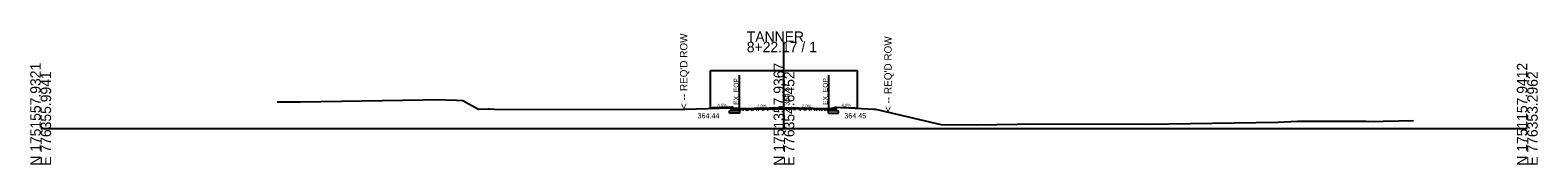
# Model space of a CAD drawing. Extents: x 774192 to 776597, y 1750236 to 1752784.
# Drawn here: x 774680.5 to 775086.2, y 1750248.9 to 1750284.7 of the extents above; entities that cross this region are included whole.
import ezdxf

# ---------------------------------------------------------------- set-up
doc = ezdxf.new("R2010")
doc.units = 0
for name, color, linetype in [('ControlPoints', 7, 'Continuous'), ('Default', 7, 'Continuous'), ('Observations', 7, 'Continuous'), ('Setups', 7, 'Continuous'), ('SHEET_BORDER_TX', 7, 'Continuous'), ('SHEET_DATE_DGN_TX', 7, 'Continuous'), ('SHEET_LOGO', 7, 'Continuous'), ('SHEET_PLOTTING_SHAPE', 7, 'Continuous'), ('SHEET_PRELIM', 7, 'Continuous'), ('SHEET_PROJ_NUMBER', 7, 'Continuous'), ('SHEET_TITLE_BLOCK_TX', 7, 'Continuous'), ('TS_BACKBONE', 7, 'Continuous'), ('TS_DIMENSIONS', 7, 'Continuous')]:
    doc.layers.add(name, color=color, linetype=linetype)

msp = doc.modelspace()

# ---------------------------------------------------------------- linework, layer by layer
at = {"layer": 'ControlPoints'}
msp.add_lwpolyline([(774746.94, 1750265.76), (774748.9, 1750265.76), (774753.28, 1750265.74), (774786.2, 1750266.31), (774789.35, 1750266.35), (774795.18, 1750266.18), (774796.95, 1750266.12), (774801.15, 1750263.79), (774803.7, 1750263.89), (774804.05, 1750263.87), (774805.45, 1750263.8), (774853.5, 1750263.73), (774869.1, 1750264.16), (774870.94, 1750264.06), (774871.3, 1750263.95), (774877.82, 1750263.83), (774883.33, 1750263.87), (774895.29, 1750263.96), (774896.21, 1750264.02), (774897.35, 1750264.29), (774907.56, 1750263.81), (774907.98, 1750263.79), (774909.08, 1750263.56), (774925.57, 1750259.68), (774935.2, 1750259.6), (774951.41, 1750259.84), (774980.99, 1750259.76), (775016.23, 1750260.32), (775021.52, 1750260.58), (775021.92, 1750260.54), (775039.87, 1750260.57), (775040.54, 1750260.5), (775052.69, 1750260.77)], dxfattribs=at)
at = {"layer": 'Default'}
for p, q in [((774883.34, 1750263.98), (774871.34, 1750263.74)), ((774895.33, 1750263.74), (774883.33, 1750263.98))]:
    msp.add_line(p, q, dxfattribs=at)
at = {"layer": 'Setups'}
for p, q in [((774883.33, 1750258.57), (774883.33, 1750281.91)), ((774683.33, 1750258.57), (774883.33, 1750258.57)), ((774883.33, 1750258.57), (775083.33, 1750258.57))]:
    msp.add_line(p, q, dxfattribs=at)
at = {"layer": 'SHEET_BORDER_TX'}
for p, q in [((774868.67, 1750262.69), (774868.67, 1750263.35)), ((774871.35, 1750262.74), (774868.67, 1750262.69)), ((774895.32, 1750262.74), (774898, 1750262.69)), ((774898, 1750262.69), (774898, 1750263.35))]:
    msp.add_line(p, q, dxfattribs=at)
for points in [[(774868.67, 1750263.35), (774871.33, 1750263.41), (774871.35, 1750262.74)], [(774895.32, 1750262.74), (774895.33, 1750263.41), (774898, 1750263.35)]]:
    msp.add_lwpolyline(points, dxfattribs=at)
at = {"layer": 'SHEET_LOGO'}
for p, q in [((774871.3, 1750272.95), (774871.3, 1750263.95)), ((774895.29, 1750272.96), (774895.29, 1750263.96))]:
    msp.add_line(p, q, dxfattribs=at)
at = {"layer": 'SHEET_PLOTTING_SHAPE'}
for p, q in [((774869.17, 1750263.36), (774869.17, 1750264.36)), ((774897.5, 1750263.36), (774897.5, 1750264.36)), ((774871.33, 1750263.41), (774869.17, 1750263.36)), ((774871.33, 1750263.91), (774871.33, 1750263.41)), ((774895.33, 1750263.91), (774895.33, 1750263.41)), ((774895.33, 1750263.41), (774897.5, 1750263.36))]:
    msp.add_line(p, q, dxfattribs=at)
at = {"layer": 'SHEET_PROJ_NUMBER'}
for p, q in [((774863.56, 1750264.01), (774863.56, 1750274.15)), ((774863.56, 1750274.15), (774903.06, 1750274.15)), ((774903.06, 1750274.15), (774903.06, 1750264.02))]:
    msp.add_line(p, q, dxfattribs=at)
at = {"layer": 'SHEET_TITLE_BLOCK_TX'}
for p, q in [((774864.17, 1750264.16), (774863.56, 1750264.01)), ((774869.17, 1750264.36), (774864.17, 1750264.16)), ((774869.67, 1750264.37), (774869.17, 1750264.36)), ((774869.67, 1750263.87), (774869.67, 1750264.37)), ((774883.33, 1750264.15), (774871.33, 1750263.91)), ((774895.33, 1750263.91), (774883.33, 1750264.15)), ((774897, 1750263.87), (774897, 1750264.37)), ((774897, 1750264.37), (774897.5, 1750264.36)), ((774897.5, 1750264.36), (774902.5, 1750264.16)), ((774902.5, 1750264.16), (774903.06, 1750264.02)), ((774871.33, 1750263.91), (774869.67, 1750263.87)), ((774895.33, 1750263.91), (774897, 1750263.87))]:
    msp.add_line(p, q, dxfattribs=at)
at = {"layer": 'TS_BACKBONE'}
for p, q in [((774864.07, 1750264.14), (774864.07, 1750264.02)), ((774865.27, 1750264.21), (774865.27, 1750264.06)), ((774865.67, 1750264.22), (774865.67, 1750264.07)), ((774866.07, 1750264.24), (774866.07, 1750264.08)), ((774866.84, 1750264.27), (774867.17, 1750264.27)), ((774867.27, 1750264.29), (774867.27, 1750264.11)), ((774867.67, 1750264.3), (774867.67, 1750264.12)), ((774868.07, 1750264.32), (774868.07, 1750264.14)), ((774868.17, 1750264.27), (774869.17, 1750264.27)), ((774869.27, 1750264.36), (774869.27, 1750263.36)), ((774878.79, 1750263.55), (774879.3, 1750264.06)), ((774878.86, 1750264.06), (774879.35, 1750263.57)), ((774880.24, 1750263.58), (774880.75, 1750264.09)), ((774880.24, 1750264.08), (774880.73, 1750263.59)), ((774881.63, 1750264.11), (774882.12, 1750263.62)), ((774881.68, 1750263.61), (774882.19, 1750264.12)), ((774883.02, 1750264.14), (774883.51, 1750263.64)), ((774883.12, 1750263.64), (774883.62, 1750264.14)), ((774884.45, 1750264.12), (774884.96, 1750263.61)), ((774884.52, 1750263.62), (774885.01, 1750264.11)), ((774885.89, 1750264.09), (774886.4, 1750263.58)), ((774885.9, 1750263.59), (774886.39, 1750264.08)), ((774887.29, 1750263.57), (774887.78, 1750264.06)), ((774887.33, 1750264.07), (774887.84, 1750263.56)), ((774897, 1750264.37), (774897, 1750264.36)), ((774897, 1750264.27), (774897.5, 1750264.27)), ((774897.4, 1750264.36), (774897.4, 1750264.36)), ((774897.61, 1750264.36), (774897.61, 1750264.28)), ((774898.01, 1750264.34), (774898.01, 1750264.26)), ((774898.41, 1750264.33), (774898.41, 1750264.24)), ((774898.5, 1750264.27), (774899.5, 1750264.27)), ((774899.61, 1750264.28), (774899.61, 1750264.19)), ((774900.01, 1750264.26), (774900.01, 1750264.17)), ((774900.41, 1750264.25), (774900.41, 1750264.15)), ((774901.61, 1750264.2), (774901.61, 1750264.09)), ((774902.01, 1750264.18), (774902.01, 1750264.07)), ((774902.41, 1750264.17), (774902.41, 1750264.05)), ((774863.67, 1750264.04), (774863.67, 1750264.01)), ((774869.67, 1750263.87), (774869.67, 1750263.37)), ((774870.07, 1750263.88), (774870.07, 1750263.38)), ((774870.17, 1750263.87), (774871.17, 1750263.87)), ((774870.17, 1750263.47), (774871.17, 1750263.47)), ((774871.27, 1750263.9), (774871.27, 1750263.4)), ((774871.58, 1750263.41), (774872.09, 1750263.92)), ((774871.92, 1750263.92), (774872.41, 1750263.43)), ((774873.02, 1750263.44), (774873.53, 1750263.95)), ((774873.31, 1750263.95), (774873.8, 1750263.45)), ((774874.46, 1750263.47), (774874.97, 1750263.98)), ((774874.7, 1750263.97), (774875.19, 1750263.48)), ((774875.91, 1750263.5), (774876.42, 1750264.01)), ((774876.08, 1750264), (774876.57, 1750263.51)), ((774877.35, 1750263.53), (774877.86, 1750264.04)), ((774877.47, 1750264.03), (774877.96, 1750263.54)), ((774888.68, 1750263.54), (774889.17, 1750264.03)), ((774888.77, 1750264.04), (774889.28, 1750263.53)), ((774890.06, 1750263.51), (774890.55, 1750264)), ((774890.22, 1750264.01), (774890.73, 1750263.5)), ((774891.45, 1750263.48), (774891.94, 1750263.97)), ((774891.66, 1750263.98), (774892.17, 1750263.47)), ((774892.84, 1750263.46), (774893.33, 1750263.95)), ((774893.1, 1750263.95), (774893.61, 1750263.44)), ((774894.22, 1750263.43), (774894.71, 1750263.92)), ((774894.55, 1750263.92), (774895.06, 1750263.41)), ((774895.33, 1750263.87), (774895.5, 1750263.87)), ((774895.33, 1750263.47), (774895.5, 1750263.47)), ((774895.61, 1750263.9), (774895.61, 1750263.4)), ((774896.01, 1750263.89), (774896.01, 1750263.39)), ((774896.41, 1750263.88), (774896.41, 1750263.38)), ((774896.5, 1750263.87), (774897.5, 1750263.87)), ((774896.5, 1750263.47), (774897.5, 1750263.47)), ((774897.4, 1750263.37), (774897.4, 1750263.36))]:
    msp.add_line(p, q, dxfattribs=at)

# ---------------------------------------------------------------- texts
at = {"layer": 'Observations'}
for s, p in [('364.44', (774860.06, 1750261.31)), ('364.45', (774899.56, 1750261.32))]:
    msp.add_text(s, height=1.4, dxfattribs=at).set_placement(p)
at = {"layer": 'Setups'}
for s, p in [('TANNER', (774873.33, 1750281.91)), ('8+22.17 / 1', (774873.33, 1750279.11))]:
    msp.add_text(s, height=2.8, dxfattribs=at).set_placement(p)
for s, p in [('N 1751557.9321', (774683.33, 1750248.57)), ('E 776355.9941', (774686.13, 1750248.57)), ('N 1751357.9367', (774883.33, 1750248.57)), ('E 776354.6452', (774886.13, 1750248.57)), ('N 1751157.9412', (775083.33, 1750248.57)), ('E 776353.2962', (775086.13, 1750248.57))]:
    msp.add_text(s, height=2.8, rotation=90, dxfattribs=at).set_placement(p)
at = {"layer": 'SHEET_DATE_DGN_TX'}
for s, rotation, p in [('4.0%', 2.2906, (774865.44, 1750264.41)), ('2.0%', 1.1458, (774876.11, 1750264.2)), ('2.0%', 358.8542, (774888.11, 1750264.25)), ('4.0%', 357.7094, (774898.79, 1750264.51))]:
    msp.add_text(s, height=0.8, rotation=rotation, dxfattribs=at).set_placement(p)
at = {"layer": 'SHEET_LOGO'}
for p in [(774871.1, 1750264.95), (774895.09, 1750264.96)]:
    msp.add_text('EX. EOP', height=1.3, rotation=90, dxfattribs=at).set_placement(p)
at = {"layer": 'SHEET_PRELIM'}
msp.add_text(' 364.57', height=1.5, rotation=90, dxfattribs=at).set_placement((774884.83, 1750264.15))
at = {"layer": 'TS_DIMENSIONS'}
for p in [(774857.34, 1750263.81), (774912.31, 1750263.04)]:
    msp.add_text("< -- REQ'D ROW", height=2, rotation=90, dxfattribs=at).set_placement(p)

doc.saveas('drawing.dxf')
